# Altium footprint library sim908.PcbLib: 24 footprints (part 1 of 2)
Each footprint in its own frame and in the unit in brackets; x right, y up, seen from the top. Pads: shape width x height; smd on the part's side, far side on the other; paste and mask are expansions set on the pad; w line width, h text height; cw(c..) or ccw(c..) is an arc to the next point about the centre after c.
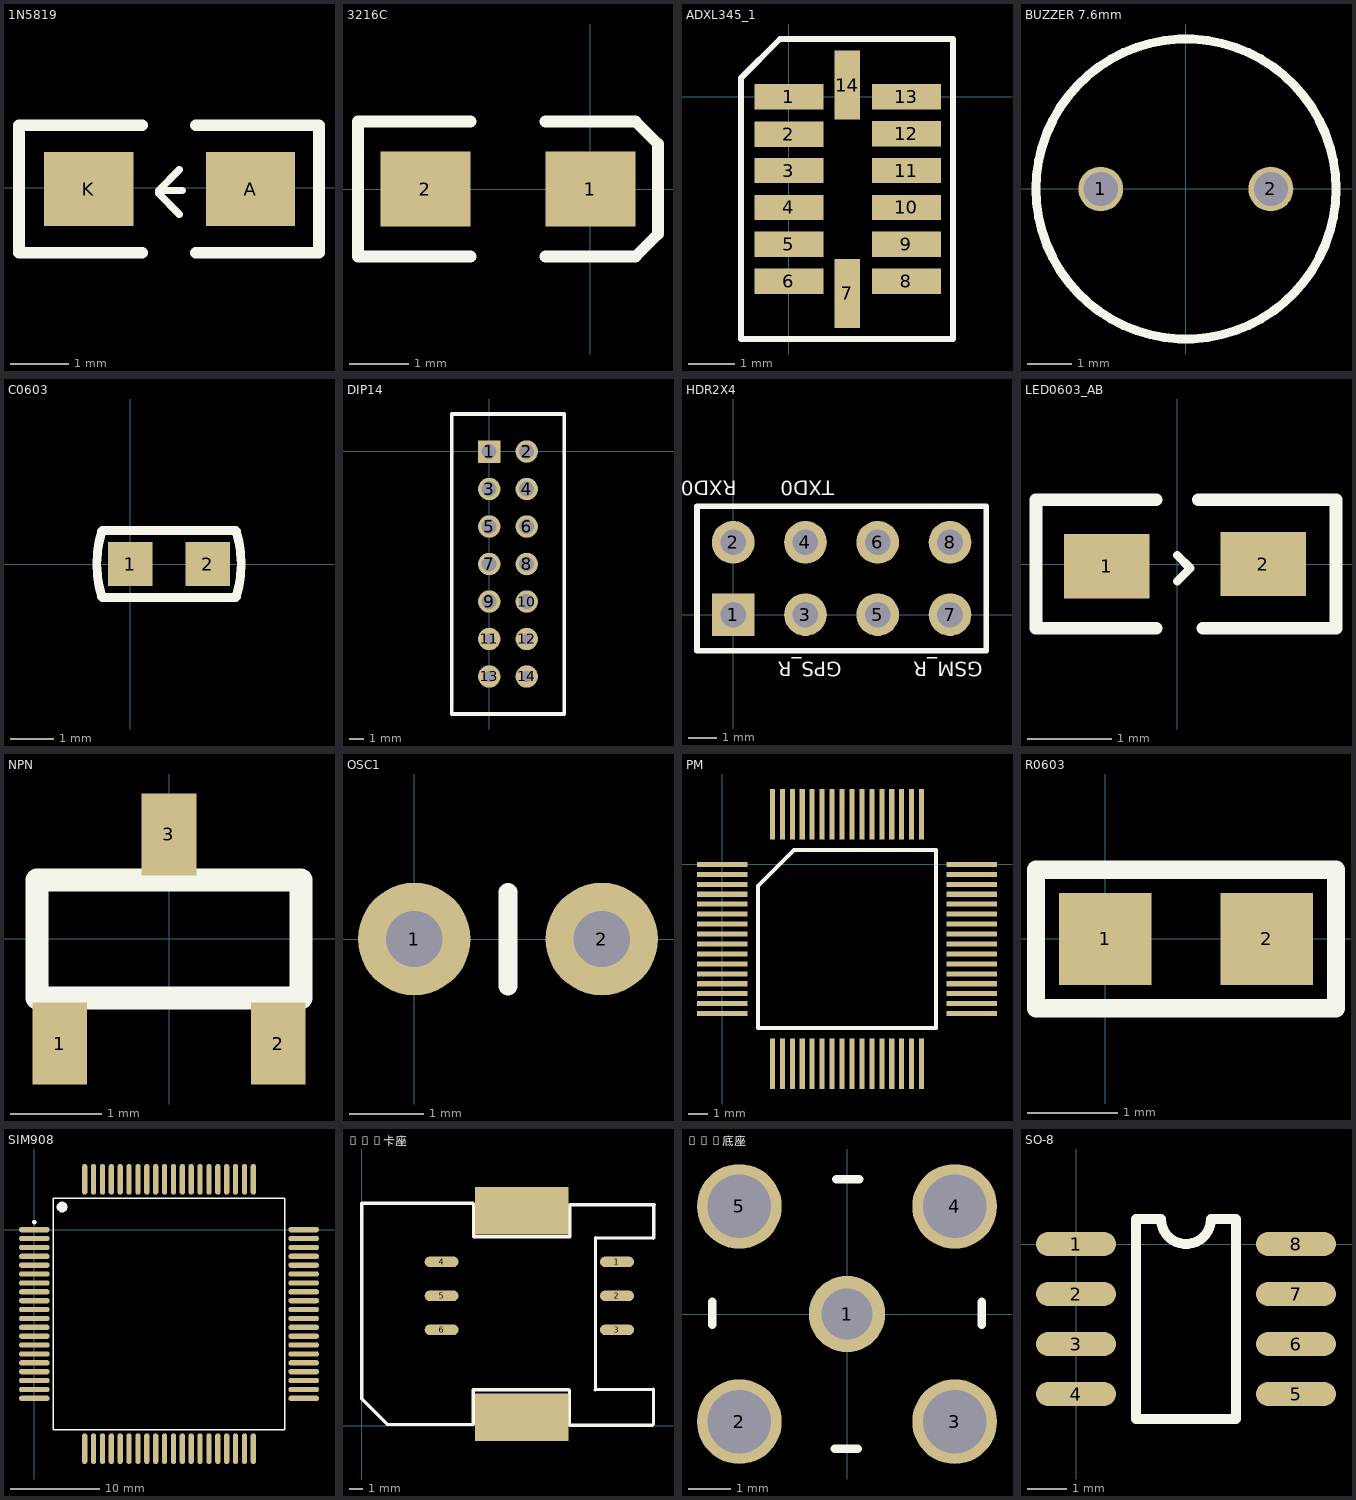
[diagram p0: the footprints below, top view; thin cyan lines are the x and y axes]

## 1N5819 [mil]
pads (2):
  rect 60x50 smd: A(-60,-1) K(-169,-1)
Top Overlay:
  lines w5: -122,-4 -108,-18 ; -122,-2 -108,12 ; -120,-2 -106,-2
  lines w7.87: -133,-44 -216,-44 -216,42 -133,42 ; -97,-44 -14,-44 -14,42 -97,42

## 3216C [mil]
height 322.83
pads (2):
  rect 60x50 smd: 1(0,0) 2(-110,0)
Top Overlay:
  lines w7.87: -80,-45 -155,-45 -155,45 -80,45 ; -30,-45 30,-45 45,-30 45,30 30,45 -30,45

## ADXL345_1 [mm]
pads (14):
  rect 1.5x0.55 smd: 1(0,0) 2(0,-0.813) 3(0,-1.6) 4(0,-2.4) 5(0,-3.2) 6(0,-4) 8(2.553,-4) 9(2.553,-3.2) 10(2.553,-2.4) 11(2.553,-1.6) 12(2.553,-0.8) 13(2.553,0)
  rect 0.55x1.5 smd: 7(1.27,-4.267) 14(1.27,0.254)
Top Overlay:
  lines w0.127: -1.041,-5.258 3.569,-5.258 3.569,1.257 -0.191,1.257 -1.041,0.406 -1.041,-5.258

## BUZZER 7.6mm [mm]
height 1.6
pads (2):
  round 1 hole 0.762: 1(-1.9,0) 2(1.9,0)
Top Overlay:
  circle w0.2: c0.004,-0.001 r3.35

## C0603 [mil]
height 322.83
pads (2):
  rect 40x40 smd: 1(0,0) 2(70,0)
Top Overlay:
  lines w8: -25.63,-29.24 cw(c70,0) -25.63,29.24 ; -25,-30 95,-30 ; -25,30 95,30 ; 95.63,-29.24 ccw(c0,0) 95.63,29.24

## DIP14 [mil]
height 322.83
pads (14):
  rect 60x60 hole 40: 1(0,0)
  round 60 hole 40: 2(100,0) 3(0,-100) 4(100,-100) 5(0,-200) 6(100,-200) 7(0,-300) 8(100,-300) 9(0,-400) 10(100,-400)
  round 60 hole 30: 11(0,-500) 12(100,-500) 13(0,-600) 14(100,-600)
Top Overlay:
  lines w10: -100,-700 -100,-500 -100,100 200,100 200,-500 200,-700 ; -100,-700 -100,-700 ; -100,-700 200,-700 ; 200,-700 200,-700

## HDR2X4 [mm] "Connector; Header; 4x2 Position"
height 8.2
pads (8):
  rect 1.5x1.5 hole 0.9: 1(0,0)
  round 1.5 hole 0.9: 2(0,2.54) 3(2.54,0) 4(2.54,2.54) 5(5.08,0) 6(5.08,2.54) 7(7.62,0) 8(7.62,2.54)
Top Overlay:
  lines w0.2: -1.27,-1.27 8.89,-1.27 8.89,3.81 -1.27,3.81 -1.27,-1.27
  text "RXD0" at 0.127,4.699 h0.51
  text "TXD0" at 3.556,4.699 h0.51
  text "GSM_R" at 8.763,-1.651 h0.51
  text "GPS_R" at 3.81,-1.651 h0.51

## LED0603_AB [mil]
height 322.83
pads (2):
  rect 40x30 smd: 1(-32.93,-1) 2(40,0)
Top Overlay:
  lines w4: 0,-8 5,-3 ; 0,4 6,-2
  lines w6: -10,-30 -66,-30 -66,30 -10,30 ; 9.9,30 74,30 74,-30 12,-30

## NPN [mm]
pads (3):
  rect 0.6x0.9 smd: 1(-1.2,-1.15) 2(1.2,-1.15) 3(0,1.15)
Top Overlay:
  lines w0.254: -1.45,-0.65 -1.45,0.65 1.45,0.65 1.45,-0.65 -1.45,-0.65

## OSC1 [mil]
height 322.83
pads (2):
  round 60 hole 30: 1(0,0) 2(100,0)
Top Overlay:
  lines w10: 50,-25 50,25

## PM [mm]
height 8.2
pads (64):
  rect 2.54x0.254 smd: 1(0,0) 2(0,-0.5) 3(0,-1) 4(0,-1.5) 5(0,-2) 6(0,-2.5) 7(0,-3) 8(0,-3.5) 9(0,-4) 10(0,-4.5) 11(0,-5) 12(0,-5.5) 13(0,-6) 14(0,-6.5) 15(0,-7) 16(0,-7.5) 33(12.54,-7.5) 34(12.54,-7) 35(12.54,-6.5) 36(12.54,-6) 37(12.54,-5.5) 38(12.54,-5) 39(12.54,-4.5) 40(12.54,-4) 41(12.54,-3.5) 42(12.54,-3) 43(12.54,-2.5) 44(12.54,-2) 45(12.54,-1.5) 46(12.54,-1) 47(12.54,-0.5) 48(12.54,0)
  rect 0.254x2.54 smd: 17(2.52,-10.02) 18(3.02,-10.02) 19(3.52,-10.02) 20(4.02,-10.02) 21(4.52,-10.02) 22(5.02,-10.02) 23(5.52,-10.02) 24(6.02,-10.02) 25(6.52,-10.02) 26(7.02,-10.02) 27(7.52,-10.02) 28(8.02,-10.02) 29(8.52,-10.02) 30(9.02,-10.02) 31(9.52,-10.02) 32(10.02,-10.02) 49(10.02,2.52) 50(9.52,2.52) 51(9.02,2.52) 52(8.52,2.52) 53(8.02,2.52) 54(7.52,2.52) 55(7.02,2.52) 56(6.52,2.52) 57(6.02,2.52) 58(5.52,2.52) 59(5.02,2.52) 60(4.52,2.52) 61(4.02,2.52) 62(3.52,2.52) 63(3.02,2.52) 64(2.52,2.52)
Top Overlay:
  lines w0.2: 1.805,-8.215 1.805,-1.09 3.61,0.715 10.735,0.715 10.735,-8.215 1.805,-8.215

## R0603 [mil]
height 322.83
pads (2):
  rect 40x40 smd: 1(0,0) 2(70,0)
Top Overlay:
  lines w8: -30,-30 -30,30 100,30 100,-30 -30,-30

## SIM908 [mm] "QFP, 80-Leads, Body 33.0x33.0mm (max), Pitch 1.00mm, IPC Medium Density"
height 3.2
pads (80):
  oval 3.45x0.6 smd: 1(0,0) 2(0,-1) 3(0,-2) 4(0,-3) 5(0,-4) 6(0,-5) 7(0,-6) 8(0,-7) 9(0,-8) 10(0,-9) 11(0,-10) 12(0,-11) 13(0,-12) 14(0,-13) 15(0,-14) 16(0,-15) 17(0,-16) 18(0,-17) 19(0,-18) 20(0,-19) 41(30.35,-19) 42(30.35,-18) 43(30.35,-17) 44(30.35,-16) 45(30.35,-15) 46(30.35,-14) 47(30.35,-13) 48(30.35,-12) 49(30.35,-11) 50(30.35,-10) 51(30.35,-9) 52(30.35,-8) 53(30.35,-7) 54(30.35,-6) 55(30.35,-5) 56(30.35,-4) 57(30.35,-3) 58(30.35,-2) 59(30.35,-1) 60(30.35,0)
  oval 0.6x3.45 smd: 21(5.675,-24.675) 22(6.675,-24.675) 23(7.675,-24.675) 24(8.675,-24.675) 25(9.675,-24.675) 26(10.675,-24.675) 27(11.675,-24.675) 28(12.675,-24.675) 29(13.675,-24.675) 30(14.675,-24.675) 31(15.675,-24.675) 32(16.675,-24.675) 33(17.675,-24.675) 34(18.675,-24.675) 35(19.675,-24.675) 36(20.675,-24.675) 37(21.675,-24.675) 38(22.675,-24.675) 39(23.675,-24.675) 40(24.675,-24.675) 61(24.675,5.675) 62(23.675,5.675) 63(22.675,5.675) 64(21.675,5.675) 65(20.675,5.675) 66(19.675,5.675) 67(18.675,5.675) 68(17.675,5.675) 69(16.675,5.675) 70(15.675,5.675) 71(14.675,5.675) 72(13.675,5.675) 73(12.675,5.675) 74(11.675,5.675) 75(10.675,5.675) 76(9.675,5.675) 77(8.675,5.675) 78(7.675,5.675) 79(6.675,5.675) 80(5.675,5.675)
Top Overlay:
  circle w0.6: c3.125,2.55 r0.3
  circle w0.25: c0,0.85 r0.125
  lines w0.2: 2.125,-22.55 28.225,-22.55 28.225,3.55 2.125,3.55 2.125,-22.55

## SIM卡座 [mm]
height 8.2
pads (8):
  oval 2.54x0.8 smd: 1(19.062,12.237) 2(19.062,9.697) 3(19.062,7.157) 4(5.954,12.237) 5(5.954,9.697) 6(5.954,7.157)
  rect 7x3.556 smd: ""(11.939,0.626) ""(11.941,16.052)
Top Overlay:
  lines w0.254: -0.013,16.606 8.291,16.606 ; -0.01,16.605 -0.01,2.007 1.892,0.105 ; 1.905,0.078 8.294,0.078 ; 8.325,0.078 8.325,2.665 15.48,2.665 ; 8.357,16.56 8.357,14.1 15.544,14.1 15.544,16.528 ; 15.512,0.014 21.709,0.014 ; 15.512,0.142 15.512,2.633 ; 15.56,16.509 21.846,16.509 21.802,16.464 21.802,14.025 ; 17.429,2.665 21.79,2.705 21.79,0.105 ; 17.461,2.673 17.461,13.973 ; 17.461,14.036 21.79,14.005

## SMA底座 [mm] "Connector; RF Coaxial, MMCX, Thru-Hole; 5 Position; Right-Angle"
height 3.8
pads (5):
  round 1.8 hole 1.2: 1(0,0)
  round 2 hole 1.5: 2(-2.54,-2.54) 3(2.54,-2.54) 4(2.54,2.54) 5(-2.54,2.54)
Top Overlay:
  lines w0.2: -3.175,-0.254 -3.175,0.286 ; -0.286,-3.175 0.254,-3.175 ; -0.254,3.175 0.286,3.175 ; 3.175,-0.254 3.175,0.286

## SO-8 [mil]
height 322.83
pads (8):
  oval 80x24 smd: 1(0,0) 2(0,-50) 3(0,-100) 4(0,-150) 5(220,-150) 6(220,-100) 7(220,-50) 8(220,0)
Top Overlay:
  lines w10: 60,-175 60,25 85,25 ccw(c110,25) 135,25 160,25 160,-175 60,-175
